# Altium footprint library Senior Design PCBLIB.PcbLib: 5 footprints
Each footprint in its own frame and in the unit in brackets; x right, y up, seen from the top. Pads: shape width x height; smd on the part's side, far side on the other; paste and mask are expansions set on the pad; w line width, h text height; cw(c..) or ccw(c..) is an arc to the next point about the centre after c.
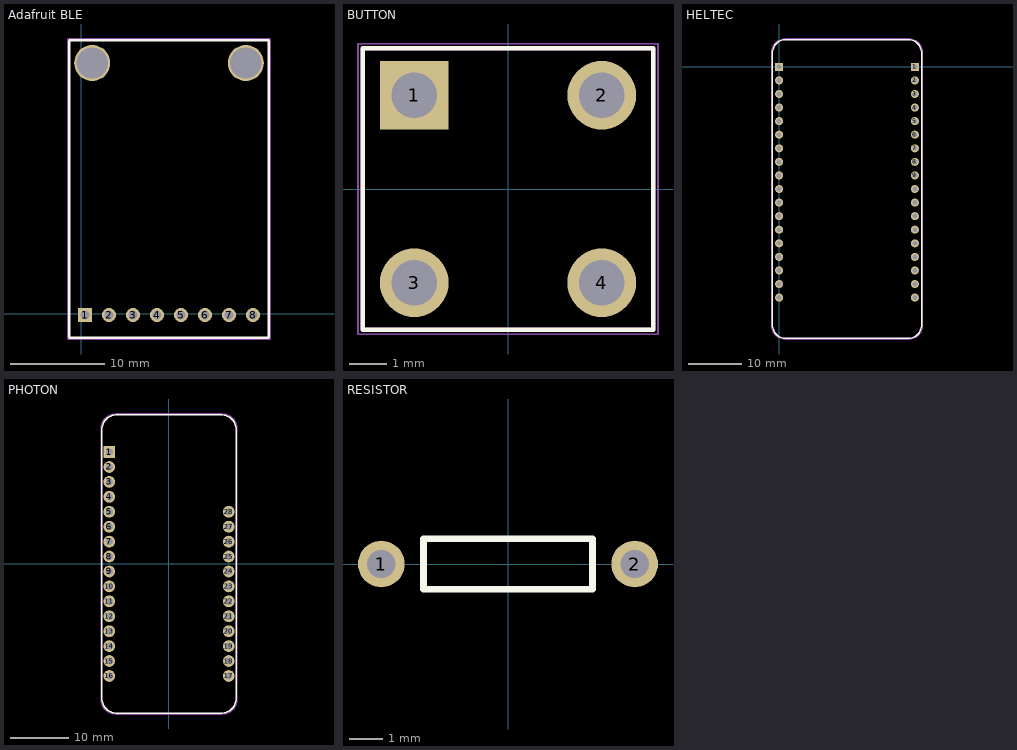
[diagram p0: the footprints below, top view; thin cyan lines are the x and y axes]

## Adafruit BLE [mm]
pads (10):
  rect 1.5x1.5 hole 0.9: 1(0.381,-0.127)
  round 1.5 hole 0.9: 2(2.921,-0.127) 3(5.461,-0.127) 4(8.001,-0.127) 5(10.541,-0.127) 6(13.081,-0.127) 7(15.621,-0.127) 8(18.161,-0.127)
  round 3.81 hole 3.302: ""(1.143,26.543) ""(17.399,26.543)
Top Overlay:
  lines w0.254: -1.27,-2.413 ccw(c-1.143,-2.413) -1.143,-2.54 19.685,-2.54 ccw(c19.685,-2.413) 19.812,-2.413 19.812,28.829 ccw(c19.685,28.829) 19.685,28.956 -1.143,28.956 ccw(c-1.143,28.829) -1.27,28.829 -1.27,-2.413
Mechanical 1:
  lines w0.254: -1.397,-2.667 -1.397,29.083 19.939,29.083 19.939,-2.667 -1.397,-2.667

## BUTTON [mm]
pads (4):
  rect 1.86x1.86 hole 1.24: 1(-2.54,2.54)
  round 1.86 hole 1.24: 2(2.54,2.54) 3(-2.54,-2.54) 4(2.54,-2.54)
Top Overlay:
  circle w0.2: c-2.54,-2.54 r0.1
  lines w0.127: -3.937,-3.81 -3.937,3.81 3.937,3.81 3.937,-3.81 -3.937,-3.81
Mechanical 13 (Mech13):
  circle w0.2: c-2.54,-2.54 r0.1
  lines w0.127: -3.937,-3.81 -3.937,3.81 3.937,3.81 3.937,-3.81 -3.937,-3.81
Mechanical 15:
  lines w0.05: -4.064,-3.937 -4.064,3.937 4.064,3.937 4.064,-3.937 -4.064,-3.937

## HELTEC [mm]
pads (36):
  rect 1.5x1.5 hole 0.9: 1(25.4,0) 36(0,0)
  round 1.5 hole 0.9: 2(25.4,-2.54) 3(25.4,-5.08) 4(25.4,-7.62) 5(25.4,-10.16) 6(25.4,-12.7) 7(25.4,-15.24) 8(25.4,-17.78) 9(25.4,-20.32) 10(25.4,-22.86) 11(25.4,-25.4) 12(25.4,-27.94) 13(25.4,-30.48) 14(25.4,-33.02) 15(25.4,-35.56) 16(25.4,-38.1) 17(25.4,-40.64) 18(25.4,-43.18) 19(0,-43.18) 20(0,-40.64) 21(0,-38.1) 22(0,-35.56) 23(0,-33.02) 24(0,-30.48) 25(0,-27.94) 26(0,-25.4) 27(0,-22.86) 28(0,-20.32) 29(0,-17.78) 30(0,-15.24) 31(0,-12.7) 32(0,-10.16) 33(0,-7.62) 34(0,-5.08) 35(0,-2.54)
Top Overlay:
  lines w0.254: -1.27,-48.26 ccw(c1.27,-48.26) 1.27,-50.8 24.13,-50.8 ccw(c24.13,-48.26) 26.67,-48.26 26.67,2.54 ccw(c24.13,2.54) 24.13,5.08 1.27,5.08 ccw(c1.27,2.54) -1.27,2.54 -1.27,-48.26
Mechanical 1:
  lines w0.254: -1.397,-48.387 ccw(c1.143,-48.387) 1.143,-50.927 24.257,-50.927 ccw(c24.257,-48.387) 26.797,-48.387 26.797,2.667 ccw(c24.257,2.667) 24.257,5.207 1.143,5.207 ccw(c1.143,2.667) -1.397,2.667 -1.397,-48.387

## PHOTON [mm]
pads (28):
  rect 2x2 hole 1.2: 1(-10.16,19.05)
  round 2 hole 1.2: 2(-10.16,16.51) 3(-10.16,13.97) 4(-10.16,11.43) 5(-10.16,8.89) 6(-10.16,6.35) 7(-10.16,3.81) 8(-10.16,1.27) 9(-10.16,-1.27) 10(-10.16,-3.81) 11(-10.16,-6.35) 12(-10.16,-8.89) 13(-10.16,-11.43) 14(-10.16,-13.97) 15(-10.16,-16.51) 16(-10.16,-19.05) 17(10.16,-19.05) 18(10.16,-16.51) 19(10.16,-13.97) 20(10.16,-11.43) 21(10.16,-8.89) 22(10.16,-6.35) 23(10.16,-3.81) 24(10.16,-1.27) 25(10.16,1.27) 26(10.16,3.81) 27(10.16,6.35) 28(10.16,8.89)
Top Overlay:
  lines w0.254: -11.43,-22.86 ccw(c-8.89,-22.86) -8.89,-25.4 8.89,-25.4 ccw(c8.89,-22.86) 11.43,-22.86 11.43,22.86 ccw(c8.89,22.86) 8.89,25.4 -8.89,25.4 ccw(c-8.89,22.86) -11.43,22.86 -11.43,-22.86
Mechanical 1:
  lines w0.254: -11.557,-22.987 ccw(c-9.017,-22.987) -9.017,-25.527 9.017,-25.527 ccw(c9.017,-22.987) 11.557,-22.987 11.557,22.987 ccw(c9.017,22.987) 9.017,25.527 -9.017,25.527 ccw(c-9.017,22.987) -11.557,22.987 -11.557,-22.987
3D body "Photon 2.step": height 7.33, standoff -9.34, extent -11.43,-25.401 11.43,26.999

## RESISTOR [mm]
pads (2):
  round 1.4 hole 0.85: 1(-3.81,0) 2(3.81,0)
Top Overlay:
  lines w0.2: -2.54,-0.762 -2.54,0.762 2.54,0.762 2.54,0 2.54,-0.762 -2.54,-0.762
